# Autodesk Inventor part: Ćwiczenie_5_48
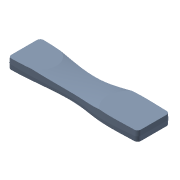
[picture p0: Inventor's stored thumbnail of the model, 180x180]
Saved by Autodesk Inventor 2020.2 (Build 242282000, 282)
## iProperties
Created: 2005-05
Part Number: Ćwiczenie_5_48
Document SubType Name: Modeling
Designer: F.Stasiak
Manufacturer: Standard
Standards Organization: Custom
Density: 1 g/cm^3
Material: Ogólny
Appearance: Stalowoniebieska - jasna
Manager: www.cadconsulting.pl
Company: Fabian Stasiak CAD Consulting
Author: F.Stasiak
Subject: Zbiór ćwiczeń. Autodesk Inventor 2020. Kurs podstawowy
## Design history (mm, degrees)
sketch "Szkic1"
  geometry: L1 (-100, 25)-(100, 25); L2 (100, 25)-(100, -25); L3 (100, -25)-(-100, -25); L4 (-100, -25)-(-100, 25); L5 (0, 25)-(0, -25); L6 (-120.429, 25)-(-79.571, 25); L7 (79.571, 25)-(120.429, 25); L8 (-100, 0)-(100, 0); L9 (-120.429, -25)-(-79.571, -25); L10 (79.571, -25)-(120.429, -25); A1 r 559.729 centre (-100, -534.729) between (-79.585, 24.628) and (-120.415, 24.628); A2 r 211.524 centre (100, 236.524) between (79.666, 25.98) and (120.334, 25.98); A3 r 559.729 centre (-100, 534.729) between (-120.415, -24.628) and (-79.585, -24.628); A4 r 211.524 centre (100, -236.524) between (120.334, -25.98) and (79.666, -25.98); 8 further points
  constraints: 20 end point, 13 symmetric about line, 11 midpoint, 6 horizontal, 4 centre point, 4 point on circle, 3 perpendicular, 2 parallel, 2 point on line, 1 coincident, 16 other
  dimensions: "d0" = 200 distance of L2.end L3.end; "d1" = 50 distance of L3.end L1.start; "d2" = 10 dimension on L6.start L6.end; "d3" = 10 dimension on L7.start L7.end; "d4" = 40 distance of point (0, -20) point (0, 20); "d5" = 40 distance from line of point (-60, -22.902) L4; "d6" = 60 distance from line of L2 point (40, -25)
extrude "Wyciągnięcie proste1" new body sketch "Szkic1" distance "d7" = 15; taper "d8" = 0 deg
sketch "Szkic3"
  geometry: L1 (100, 25)-(100, 25); L2 (100, 25)-(75, 25); L3 (75, 25)-(75, -25); L4 (75, -25)-(100, -25); A1 r 25 centre (75, 0) between (75, 25) and (75, -25)
  constraints: 8 end point, 2 point on circle, 2 tangent, 1 centre point, 1 parallel, 1 perpendicular
  dimensions: "d13" = 25 distance of L1.end L2.end
sketch "Szkic4"
  geometry: L1 (-100, -25)-(-100, 25) reference; L2 (-100, 25)-(-50, 30); L3 (-50, 30)-(-50, -30); L4 (-50, -30)-(-100, -25); L5 (-100, 0)-(-50, 0); A1 r 31.906 centre (-60.861, 0) between (-50, -30) and (-50, 30)
  constraints: 8 end point, 2 midpoint, 2 point on circle, 1 centre point, 1 horizontal, 1 parallel
  dimensions: "d14" = 60 distance of L2.end L3.end; "d15" = 50 distance between parallel lines of L3 L1
node "Punkt konstrukcyjny1"
node "Punkt konstrukcyjny2"
sketch "Szkic5"
  geometry: 3 further points
  constraints: 3 other
feature "PowWyciągnięciaZłożonego1" sketch "Szkic5" dims "d16" = 0, "d17" = 90 deg, "d18" = 0, "d19" = 90 deg, "d20" = 0, "d21" = 90 deg
feature "Podział1"
sketch "Szkic6"
  geometry: L1 (-100, 0)-(-100, 15) reference; L2 (100, 0)-(100, 15) reference; 3 further points
  constraints: 2 midpoint, 3 other
feature "Podział2" sketch "Szkic6"
feature "Szkic powierzchni1" dims angle "d22" = -2.5 deg
feature "Szkic powierzchni2" dims angle "d23" = 1.5 deg
fillet "Zaokrąglenie1" dims "d24" = 5
node "Bryła1"
node "Korpusy bryłowe"
node "Korpusy powierzchniowe"
body "Srf1"
